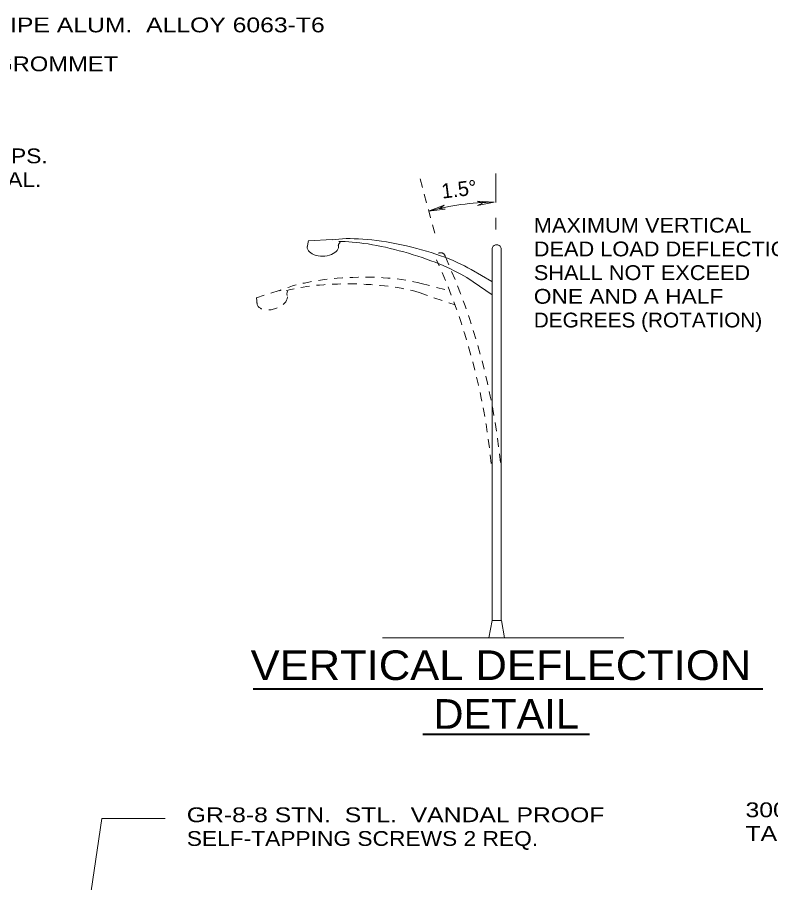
# Model space of a CAD drawing. Extents: x 312583 to 312854, y 144418 to 144597.
# Drawn here: x 312690.06 to 312728.78, y 144500.43 to 144544.89 of the extents above; entities that cross this region are included whole.
import ezdxf
from ezdxf.enums import TextEntityAlignment as Align

# ---------------------------------------------------------------- set-up
doc = ezdxf.new("R2010")
doc.units = 0
doc.header["$LTSCALE"] = 0.3
doc.linetypes.add('SHORT_DASHED', pattern=[2.7, 1.5, -1.2])
doc.layers.add('1', color=7, linetype='Continuous', lineweight=35)

msp = doc.modelspace()

# ---------------------------------------------------------------- linework, layer by layer
at = {"layer": '1', "linetype": 'SHORT_DASHED', "lineweight": 13}
for p, q in [((312711.5091, 144533.7985), (312710.7085, 144536.7875)), ((312710.8152, 144531.2137), (312712.2792, 144530.8324)), ((312703.5257, 144530.8553), (312702.3591, 144530.4817)), ((312710.7085, 144530.7485), (312712.5537, 144530.1081))]:
    msp.add_line(p, q, dxfattribs=at)
at = {"layer": '1', "lineweight": 13}
for p, q in [((312714.6582, 144535.3693), (312714.6582, 144536.8562)), ((312713.6898, 144535.4379), (312713.972, 144535.3464)), ((312714.5591, 144535.3845), (312713.6898, 144535.4379)), ((312714.5591, 144535.3845), (312713.7051, 144535.2244)), ((312713.7051, 144535.2244), (312713.972, 144535.3464)), ((312711.1888, 144534.9271), (312711.9971, 144535.2321)), ((312711.1888, 144534.9271), (312712.0505, 144535.0262)), ((312711.9971, 144535.2321), (312711.7607, 144535.0643)), ((312712.0505, 144535.0262), (312711.7607, 144535.0643)), ((312714.6582, 144533.9815), (312714.6582, 144534.5763)), ((312704.9592, 144533.0665), (312705.0202, 144533.4249)), ((312706.2478, 144533.4707), (312705.0202, 144533.4097)), ((312714.9327, 144513.9049), (312714.9327, 144532.9674)), ((312713.3772, 144531.9304), (312714.4524, 144531.3204)), ((312713.1561, 144531.5111), (312714.46, 144530.6265)), ((312702.3896, 144530.1309), (312702.3515, 144530.4969)), ((312714.46, 144513.8973), (312714.2998, 144513.0128)), ((312715.1005, 144513.0128), (312714.9404, 144513.9049)), ((312721.2234, 144513.0052), (312708.8251, 144513.0052)), ((312715.1005, 144513.0128), (312714.2998, 144513.0128)), ((312694.401, 144503.7339), (312692.1135, 144488.3162)), ((312694.401, 144503.7339), (312697.6569, 144503.7339))]:
    msp.add_line(p, q, dxfattribs=at)
at = {"layer": '1', "lineweight": 40}
for p, q in [((312728.3764, 144510.3745), (312702.1734, 144510.3745)), ((312719.4647, 144508.0489), (312710.9077, 144508.0489))]:
    msp.add_line(p, q, dxfattribs=at)
at = {"layer": '1', "lineweight": 13}
for points in [[(312706.5681, 144533.1123), (312706.5681, 144533.2114), (312706.6444, 144533.3334)], [(312714.9327, 144513.9049), (312714.46, 144513.9049), (312714.46, 144532.9674)], [(312703.9298, 144530.5884), (312703.907, 144530.6875), (312703.9451, 144530.8248)]]:
    msp.add_lwpolyline(points, dxfattribs=at)
for centre, radius, start, end in [((312714.6582, 144522.0408), 13.3438, 90.4293, 105.06849), ((312714.6963, 144532.9674), 0.2364, 352.14669, 187.35238)]:
    msp.add_arc(centre, radius, start, end, dxfattribs=at)
at = {"layer": '1', "linetype": 'SHORT_DASHED', "lineweight": 13}
for centre, radius, start, end in [((312711.8179, 144532.5556), 0.2364, 7.14669, 202.35238), ((312680.7825, 144518.5471), 33.8066, 5.81096, 24.23139), ((312680.7825, 144518.5471), 34.2806, 5.81096, 24.23139)]:
    msp.add_arc(centre, radius, start, end, dxfattribs=at)
at = {"layer": '1', "lineweight": 13}
for centre, major_axis, ratio, start_param, end_param in [((312709.8328, 144531.9431), (-4.4261, 1.0318), 0.268635, 3.8483725, 5.7132841), ((312705.7637, 144533.0894), (-0.8044, -0.0229), 0.588769, 6.0717954, 9.5838516), ((312709.7616, 144531.7778), (-4.2115, 1.2174), 0.241787, 3.8483725, 5.6365717)]:
    msp.add_ellipse(centre, major_axis=major_axis, ratio=ratio, start_param=start_param, end_param=end_param, dxfattribs=at)
at = {"layer": '1', "linetype": 'SHORT_DASHED', "lineweight": 13}
for centre, major_axis, ratio, start_param, end_param in [((312707.3852, 144530.3074), (-4.5424, -0.1489), 0.268635, 3.8483725, 5.7132841), ((312707.3592, 144530.1293), (-4.383, 0.0859), 0.241787, 3.8483725, 5.6365717), ((312703.158, 144530.3615), (-0.7711, -0.2303), 0.588769, 6.0717954, 9.5838516)]:
    msp.add_ellipse(centre, major_axis=major_axis, ratio=ratio, start_param=start_param, end_param=end_param, dxfattribs=at)

# ---------------------------------------------------------------- texts
at = {"layer": '1'}
for s, width, p in [('OR 32 MM SCH. 40 PIPE ALUM.  ALLOY 6063-T6', 1.25, (312677.1946, 144544.1144)), ('DRILL FOR 25 MM I.D.  RUBBER GROMMET', 1.2, (312670.1034, 144542.1142)), ('ALUMINUM SPLIT CAST OR EXTRUDED CLAMPS.', 1.15, (312664.0872, 144537.3867)), ('DESIGN SHALL BE SUBMITTED FOR APPROVAL.', 1.15, (312664.0872, 144536.1692)), ('MAXIMUM VERTICAL', 1.1, (312716.6026, 144533.8239)), ('DEAD LOAD DEFLECTION', 1.1, (312716.6026, 144532.6064)), ('SHALL NOT EXCEED', 1.1, (312716.6026, 144531.3889)), ('ONE AND A HALF', 1.15, (312716.6026, 144530.1714)), ('DEGREES (ROTATION)', 1.05, (312716.6026, 144528.9539)), ('GR-8-8 STN.  STL.  VANDAL PROOF', 1.25, (312698.7701, 144503.5382)), (' 3003-H14 ALUM.  ALLOY', 1.25, (312727.1304, 144503.7946)), (' TAG HOLDER 0.6 MM THK.', 1.25, (312727.1304, 144502.5771)), ('SELF-TAPPING SCREWS 2 REQ.', 1.15, (312698.7701, 144502.3207))]:
    msp.add_text(s, height=0.76, dxfattribs=dict(at, width=width)).set_placement(p)
msp.add_text('1.5°', height=0.76, rotation=7, dxfattribs=at).set_placement((312711.9045, 144535.5697))
for s, width, p in [('VERTICAL DEFLECTION', 1.1, (312714.9103, 144510.8431)), ('DETAIL', 1.05, (312715.1859, 144508.3387))]:
    msp.add_text(s, height=1.52, dxfattribs=dict(at, width=width)).set_placement(p, align=Align.CENTER)

doc.saveas('drawing.dxf')
